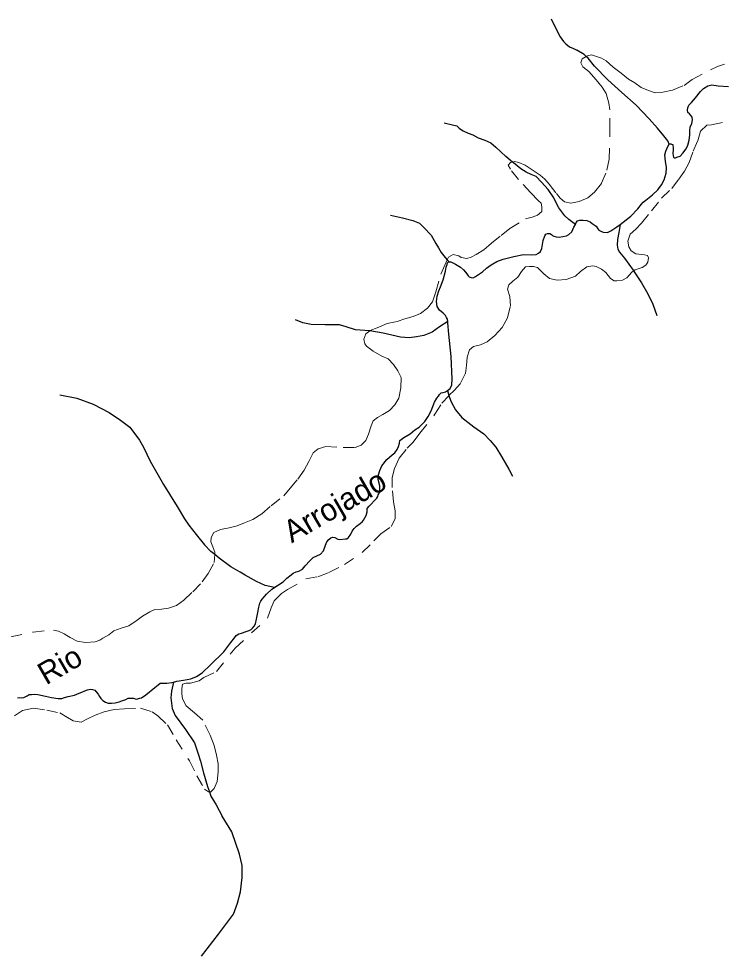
# Model space of a CAD drawing. Extents: x 391.8 to 446, y 8452 to 8507.5.
# Drawn here: x 400.69 to 407.03, y 8463.36 to 8471.81 of the extents above; entities that cross this region are included whole.
import ezdxf
from ezdxf.enums import TextEntityAlignment as Align

# ---------------------------------------------------------------- set-up
doc = ezdxf.new("R2010")
doc.units = 0
doc.header["$LTSCALE"] = 0.064
doc.linetypes.add('LONG_DASHED', pattern=[7.5, 6, -1.5])
doc.linetypes.add('SHORT_DASHED', pattern=[2.7, 1.5, -1.2])
for name, color, linetype, lineweight in [('21', 7, 'SHORT_DASHED', 13), ('7', 7, 'Continuous', 25), ('9', 7, 'LONG_DASHED', 25)]:
    doc.layers.add(name, color=color, linetype=linetype, lineweight=lineweight)
doc.layers.add('61', color=7, linetype='Continuous')

msp = doc.modelspace()

# ---------------------------------------------------------------- linework, layer by layer
at = {"layer": '21'}
for points in [[(405.1393, 8470.5226), (405.1582, 8470.5264), (405.1966, 8470.5187), (405.2541, 8470.4957), (405.3154, 8470.4536), (405.3882, 8470.4038), (405.4304, 8470.3694), (405.4687, 8470.3235), (405.5339, 8470.2392), (405.5684, 8470.1971), (405.6067, 8470.1627), (405.6642, 8470.1512), (405.7409, 8470.1665), (405.8176, 8470.2009), (405.8789, 8470.2507), (405.9402, 8470.3311), (405.9901, 8470.4498), (406.0092, 8470.5493), (406.0169, 8470.8173), (406.0144, 8470.995), (406.0067, 8471.0524), (405.9837, 8471.1405), (405.9454, 8471.1979), (405.8917, 8471.263), (405.8266, 8471.3396), (405.7729, 8471.3817), (405.7537, 8471.4161), (405.7652, 8471.4544), (405.8035, 8471.475)], [(405.8035, 8471.475), (405.8151, 8471.4812), (405.8496, 8471.4889), (405.9416, 8471.4582), (405.9837, 8471.4353), (406.0451, 8471.3778), (406.1179, 8471.3243), (406.1831, 8471.2707), (406.2406, 8471.2362), (406.2981, 8471.1941), (406.3632, 8471.1673), (406.4246, 8471.1482), (406.4936, 8471.152), (406.5817, 8471.1711), (406.6852, 8471.2132), (406.7581, 8471.2668), (406.9229, 8471.3549), (406.9842, 8471.3855), (407.0494, 8471.4046)], [(406.2294, 8469.5409), (406.2454, 8469.5516), (406.3076, 8469.5724), (406.3387, 8469.5931), (406.3594, 8469.6189), (406.3646, 8469.6604), (406.3542, 8469.6811), (406.3283, 8469.6862), (406.2506, 8469.6966), (406.2091, 8469.7225), (406.1884, 8469.7587), (406.178, 8469.8105), (406.1987, 8469.8726), (406.2506, 8469.9192), (406.3024, 8469.971), (406.3923, 8470.0826), (406.4804, 8470.1965), (406.5737, 8470.2845), (406.6359, 8470.3673), (406.6878, 8470.4398), (406.7292, 8470.5175), (406.7655, 8470.621), (406.807, 8470.7142), (406.8329, 8470.8022), (406.8899, 8470.854), (406.9314, 8470.8592), (407.0351, 8470.8799)], [(404.5512, 8469.642), (404.5627, 8469.6662), (404.6048, 8469.6892), (404.6547, 8469.6777), (404.6777, 8469.6624), (404.7275, 8469.6547), (404.7658, 8469.6662), (404.8118, 8469.6892), (404.8808, 8469.7313), (404.9498, 8469.7925), (405.038, 8469.8615), (405.1147, 8469.9227), (405.2565, 8470.0108), (405.3158, 8470.0246), (405.3656, 8470.0437), (405.4039, 8470.0782), (405.4039, 8470.1203), (405.3963, 8470.1509), (405.3694, 8470.1777), (405.3043, 8470.2466), (405.1931, 8470.3653), (405.1203, 8470.4572), (405.1007, 8470.4957), (405.1199, 8470.5187), (405.1393, 8470.5226)], [(403.8528, 8469.0021), (403.8572, 8469.0056), (403.9185, 8469.0286), (404.0105, 8469.0669), (404.0987, 8469.086), (404.1677, 8469.109), (404.2444, 8469.1319), (404.3095, 8469.1587), (404.3748, 8469.2068), (404.417, 8469.2642), (404.4477, 8469.3523), (404.4937, 8469.5131), (404.5282, 8469.5935), (404.5512, 8469.642)], [(404.7516, 8468.8299), (404.7879, 8468.861), (404.8501, 8468.8765), (404.9123, 8468.9024), (404.9797, 8468.9593), (405.0471, 8469.0318), (405.0937, 8469.1198), (405.1196, 8469.2234), (405.1145, 8469.3114), (405.0946, 8469.3756), (405.1049, 8469.417), (405.1412, 8469.4481), (405.1879, 8469.4843), (405.219, 8469.5361), (405.2553, 8469.5775), (405.2916, 8469.5827), (405.3278, 8469.5827), (405.3641, 8469.5724), (405.3952, 8469.5413), (405.4212, 8469.5154), (405.473, 8469.474), (405.5404, 8469.4585), (405.6233, 8469.4636), (405.7063, 8469.4947), (405.7529, 8469.5361), (405.8099, 8469.5775), (405.8618, 8469.5879), (405.8929, 8469.5827), (405.9395, 8469.5568), (405.981, 8469.5258), (406.0225, 8469.474), (406.0536, 8469.4533), (406.0795, 8469.4533), (406.1313, 8469.4585), (406.1676, 8469.4792), (406.2143, 8469.5309), (406.2294, 8469.5409)], [(402.4571, 8466.9837), (402.459, 8467.0068), (402.4399, 8467.0527), (402.4207, 8467.0987), (402.4245, 8467.137), (402.4475, 8467.1829), (402.5089, 8467.2097), (402.5855, 8467.225), (402.6584, 8467.2442), (402.7235, 8467.271), (402.8002, 8467.3016), (402.8807, 8467.3513), (402.965, 8467.4241), (403.078, 8467.5142), (403.1355, 8467.5831), (403.2045, 8467.6635), (403.262, 8467.7438), (403.3042, 8467.8242), (403.3425, 8467.9008), (403.3885, 8467.9391), (403.4575, 8467.9582), (403.6147, 8467.9506), (403.722, 8467.9506), (403.7757, 8467.9697), (403.8178, 8468.0118), (403.8408, 8468.0693), (403.8649, 8468.1442), (403.884, 8468.1902), (403.9224, 8468.2208), (403.9722, 8468.2476), (404.0297, 8468.2821), (404.0795, 8468.3357), (404.114, 8468.3931), (404.1332, 8468.4888), (404.137, 8468.5807), (404.1064, 8468.6419), (404.068, 8468.6993), (404.0182, 8468.7491), (403.9607, 8468.7721), (403.884, 8468.818), (403.8227, 8468.864), (403.8074, 8468.8831), (403.7997, 8468.9252), (403.8189, 8468.975), (403.8528, 8469.0021)], [(404.5666, 8468.4174), (404.6168, 8468.4675), (404.6687, 8468.5245), (404.7153, 8468.6177), (404.7257, 8468.6901), (404.7309, 8468.7626), (404.7516, 8468.8299)], [(402.4086, 8464.8442), (402.421, 8464.8442), (402.4521, 8464.8753), (402.478, 8464.9374), (402.4884, 8465.0254), (402.4884, 8465.0979), (402.4728, 8465.1756), (402.4521, 8465.2636), (402.4158, 8465.3568), (402.3484, 8465.4914), (402.2758, 8465.5587), (402.1981, 8465.6208), (402.167, 8465.6829), (402.1618, 8465.7295), (402.1619, 8465.7733), (402.1671, 8465.8147), (402.1982, 8465.8251), (402.2397, 8465.8251), (402.3175, 8465.8458), (402.3589, 8465.8768), (402.473, 8465.929), (402.6418, 8466.1418), (402.9336, 8466.4116), (402.9641, 8466.5051), (402.9922, 8466.5677), (403.0346, 8466.6088), (403.0568, 8466.6322), (403.113, 8466.6682), (403.2774, 8466.7644), (403.3862, 8466.7851), (403.4847, 8466.8214), (403.6247, 8466.8938), (403.7854, 8467.0026), (403.8904, 8467.1087), (403.9526, 8467.1708), (404.0459, 8467.2381), (404.0822, 8467.3054), (404.0822, 8467.3779), (404.0667, 8467.4607), (404.0563, 8467.5902), (404.0563, 8467.6782), (404.077, 8467.761), (404.1185, 8467.8542), (404.1911, 8467.9422), (404.2429, 8467.9991), (404.3058, 8468.0792), (404.4406, 8468.2501), (404.5028, 8468.3485), (404.565, 8468.4158), (404.5666, 8468.4174)], [(400.6211, 8466.243), (400.8205, 8466.2851), (401.0045, 8466.3043), (401.0505, 8466.2928), (401.1003, 8466.2698), (401.1233, 8466.2545), (401.154, 8466.2354), (401.2191, 8466.2047), (401.292, 8466.1933), (401.3801, 8466.1971), (401.4223, 8466.2124), (401.4491, 8466.2315), (401.5028, 8466.2622), (401.5488, 8466.2966), (401.614, 8466.3196), (401.683, 8466.3426), (401.7596, 8466.3923), (401.8056, 8466.4306), (401.8708, 8466.4689), (401.9184, 8466.4885), (401.9759, 8466.4924), (402.0411, 8466.5), (402.1139, 8466.5268), (402.1791, 8466.5728), (402.2596, 8466.6493), (402.3439, 8466.7374), (402.3976, 8466.8139), (402.4512, 8466.9135), (402.4571, 8466.9837)], [(400.6529, 8465.5313), (400.7255, 8465.5779), (400.824, 8465.5986), (400.9432, 8465.583), (401.0624, 8465.5571), (401.1298, 8465.5157), (401.1816, 8465.4847), (401.2542, 8465.4743), (401.3061, 8465.5002), (401.3786, 8465.5364), (401.4616, 8465.5675), (401.5497, 8465.5882), (401.643, 8465.5934), (401.7882, 8465.5986), (401.8918, 8465.5675), (401.9437, 8465.5313), (402.0318, 8465.4484), (402.1099, 8465.3154), (402.2292, 8465.1238), (402.2966, 8464.9892), (402.3639, 8464.8701), (402.4002, 8464.8442), (402.4086, 8464.8442)]]:
    msp.add_lwpolyline(points, dxfattribs=at)
at = {"layer": '7'}
for points in [[(405.8035, 8471.475), (405.7831, 8471.4933), (405.718, 8471.5316)], [(406.5506, 8470.6848), (406.5376, 8470.7131), (406.5031, 8470.759), (406.4456, 8470.8278), (406.369, 8470.912), (406.2542, 8471.0344), (406.1239, 8471.1491), (405.9976, 8471.2638), (405.8789, 8471.3862), (405.8214, 8471.4589), (405.8035, 8471.475)], [(406.5506, 8470.6848), (406.5558, 8470.6874), (406.5662, 8470.6874), (406.5714, 8470.6848), (406.5818, 8470.6796), (406.5844, 8470.6719), (406.587, 8470.6537), (406.587, 8470.6303), (406.5844, 8470.6044), (406.587, 8470.5784), (406.5896, 8470.5655), (406.5974, 8470.5603), (406.6078, 8470.5603), (406.6208, 8470.5655), (406.6493, 8470.5758), (406.6727, 8470.6044), (406.7039, 8470.6433), (406.7169, 8470.6744), (406.7299, 8470.7212), (406.7351, 8470.7653), (406.7377, 8470.8068), (406.7403, 8470.8379), (406.7533, 8470.8717), (406.7611, 8470.9028), (406.7585, 8470.9262), (406.7481, 8470.9392), (406.7325, 8470.9573), (406.7195, 8470.9703), (406.7143, 8470.9911), (406.7195, 8471.0118), (406.7273, 8471.0352), (406.7507, 8471.0611), (406.7871, 8471.1027), (406.832, 8471.158), (406.8606, 8471.1865), (406.8995, 8471.2099), (406.9333, 8471.2176), (406.9905, 8471.2099), (407.084, 8471.2047)], [(405.1393, 8470.5226), (405.0792, 8470.5726), (404.9884, 8470.6557)], [(406.1076, 8469.9592), (406.2063, 8470.0336), (406.2687, 8470.1011), (406.2999, 8470.1426), (406.3155, 8470.1608), (406.3389, 8470.179), (406.3999, 8470.2266), (406.4467, 8470.2733), (406.4805, 8470.3174), (406.5064, 8470.3615), (406.5246, 8470.4212), (406.5272, 8470.4731), (406.5168, 8470.5302), (406.5116, 8470.5873), (406.5194, 8470.621), (406.5376, 8470.6641), (406.5506, 8470.6848)], [(405.7074, 8469.961), (405.6475, 8470.0052), (405.6097, 8470.0392), (405.556, 8470.1116), (405.5068, 8470.2098), (405.4614, 8470.2741), (405.4008, 8470.3421), (405.3516, 8470.3912), (405.3062, 8470.4101), (405.2608, 8470.4328), (405.2154, 8470.463), (405.1473, 8470.5159), (405.1393, 8470.5226)], [(404.5678, 8469.6233), (404.5834, 8469.6233), (404.625, 8469.6026), (404.6692, 8469.5766), (404.6978, 8469.5507), (404.716, 8469.5299), (404.7263, 8469.5143), (404.7393, 8469.4962), (404.7497, 8469.4884), (404.7653, 8469.4806), (404.7861, 8469.478), (404.8043, 8469.491), (404.8693, 8469.5325), (404.9056, 8469.5662), (404.9472, 8469.5974), (404.9966, 8469.6259), (405.0538, 8469.6467), (405.1525, 8469.6726), (405.2383, 8469.6882), (405.3119, 8469.6855), (405.3535, 8469.6907), (405.3743, 8469.701), (405.3925, 8469.7166), (405.4029, 8469.7426), (405.4159, 8469.8152), (405.4289, 8469.8567), (405.4393, 8469.8723), (405.4549, 8469.8775), (405.4756, 8469.8775), (405.4912, 8469.8697), (405.499, 8469.8619), (405.512, 8469.8541), (405.5328, 8469.849), (405.5588, 8469.8464), (405.5926, 8469.8516), (405.6264, 8469.8567), (405.6471, 8469.8697), (405.6731, 8469.8931), (405.6913, 8469.9346), (405.7074, 8469.961)], [(405.7074, 8469.961), (405.7126, 8469.9791), (405.7256, 8469.9921), (405.7464, 8469.9999), (405.775, 8469.9999), (405.8088, 8469.9947), (405.8374, 8469.9843), (405.8555, 8469.9688), (405.8919, 8469.9454), (405.9075, 8469.922), (405.9179, 8469.9091), (405.9361, 8469.8987), (405.9569, 8469.8909), (405.9959, 8469.8883), (406.0244, 8469.9039), (406.079, 8469.9376), (406.1076, 8469.9592)], [(406.1076, 8469.9592), (406.0972, 8469.8882), (406.0861, 8469.8246), (406.0833, 8469.7748), (406.0889, 8469.7389), (406.1027, 8469.7112), (406.147, 8469.6559), (406.2245, 8469.5481), (406.2294, 8469.5409)], [(404.5557, 8469.0857), (404.5523, 8469.1076), (404.5445, 8469.1206), (404.5367, 8469.1388), (404.5159, 8469.1595), (404.4821, 8469.1881), (404.4613, 8469.2218), (404.4535, 8469.2659), (404.4613, 8469.3126), (404.4743, 8469.362), (404.4899, 8469.3983), (404.5159, 8469.4606), (404.5341, 8469.5403), (404.5418, 8469.574), (404.5496, 8469.6), (404.5548, 8469.6129), (404.56, 8469.6207), (404.5678, 8469.6233)], [(406.2294, 8469.5409), (406.302, 8469.4347), (406.3574, 8469.3352), (406.4017, 8469.2412), (406.4377, 8469.1389)], [(404.555, 8468.4625), (404.5782, 8468.4805), (404.5938, 8468.5143), (404.5964, 8468.5662), (404.586, 8468.7686), (404.5652, 8468.971), (404.5575, 8469.0739), (404.5557, 8469.0857)], [(402.9939, 8466.6872), (402.9985, 8466.6901), (403.0323, 8466.7109), (403.0739, 8466.7394), (403.1076, 8466.7706), (403.144, 8466.8017), (403.1648, 8466.8173), (403.1908, 8466.8277), (403.2142, 8466.8355), (403.248, 8466.8536), (403.2713, 8466.8822), (403.3129, 8466.9289), (403.3441, 8466.9574), (403.3779, 8466.973), (403.4091, 8466.9886), (403.4351, 8467.0171), (403.4532, 8467.069), (403.4669, 8467.0984), (403.4851, 8467.1191), (403.5033, 8467.1347), (403.5189, 8467.1399), (403.5397, 8467.1373), (403.5656, 8467.1243), (403.5838, 8467.1191), (403.6335, 8467.1251), (403.6465, 8467.1277), (403.662, 8467.1381), (403.6828, 8467.1692), (403.6958, 8467.1952), (403.714, 8467.2185), (403.7348, 8467.2393), (403.766, 8467.2652), (403.7868, 8467.2834), (403.7972, 8467.2938), (403.8102, 8467.3145), (403.8206, 8467.3353), (403.8284, 8467.369), (403.831, 8467.4002), (403.8465, 8467.4209), (403.8673, 8467.4391), (403.8933, 8467.4702), (403.9167, 8467.4936), (403.9245, 8467.5066), (403.9297, 8467.5222), (403.9427, 8467.5481), (403.9453, 8467.5792), (403.9427, 8467.6052), (403.9297, 8467.6623), (403.9323, 8467.7038), (403.9427, 8467.7427), (403.9615, 8467.7857), (404.0057, 8467.8402), (404.055, 8467.8843), (404.0784, 8467.9025), (404.0992, 8467.931), (404.1122, 8467.9596), (404.12, 8467.9881), (404.1252, 8468.0115), (404.1356, 8468.0219), (404.1616, 8468.04), (404.2162, 8468.0738), (404.2603, 8468.1075), (404.2993, 8468.1334), (404.3487, 8468.1828), (404.3799, 8468.2295), (404.4058, 8468.2788), (404.4379, 8468.3585), (404.4587, 8468.3949), (404.4717, 8468.413), (404.4821, 8468.4286), (404.4951, 8468.4416), (404.5133, 8468.4468), (404.5367, 8468.452), (404.5548, 8468.4623), (404.555, 8468.4625)], [(402.4571, 8466.9837), (402.4219, 8467.0118), (402.3638, 8467.0734)], [(402.6848, 8466.8258), (402.6024, 8466.8736), (402.4971, 8466.9517), (402.4571, 8466.9837)], [(402.9939, 8466.6872), (402.9123, 8466.7053), (402.8341, 8466.7414), (402.7318, 8466.7985), (402.6848, 8466.8258)], [(402.0852, 8465.8352), (402.1166, 8465.8422), (402.1763, 8465.8526), (402.2413, 8465.8656), (402.2933, 8465.8863), (402.3426, 8465.9175), (402.4182, 8465.9903), (402.5378, 8466.1071), (402.6027, 8466.1927), (402.6353, 8466.2345), (402.6513, 8466.255), (402.6747, 8466.2696), (402.6981, 8466.2769), (402.7405, 8466.2915), (402.7668, 8466.3002), (402.7843, 8466.3104), (402.7975, 8466.3206), (402.8121, 8466.3382), (402.8238, 8466.36), (402.834, 8466.4024), (402.8442, 8466.4622), (402.853, 8466.5104), (402.8632, 8466.5468), (402.8734, 8466.5658), (402.8837, 8466.5833), (402.9056, 8466.6052), (402.9246, 8466.6286), (402.9699, 8466.672), (402.9939, 8466.6872)], [(400.6801, 8465.6937), (400.6957, 8465.6963), (400.7139, 8465.6937), (400.7373, 8465.6963), (400.7554, 8465.7041), (400.7658, 8465.7118), (400.784, 8465.7222), (400.8048, 8465.7222), (400.8308, 8465.7248), (400.862, 8465.7222), (400.9326, 8465.709), (400.9872, 8465.696), (401.047, 8465.6883), (401.0807, 8465.6883), (401.1041, 8465.696), (401.1379, 8465.7038), (401.1925, 8465.7168), (401.2366, 8465.735), (401.26, 8465.7454), (401.286, 8465.7557), (401.312, 8465.7661), (401.3354, 8465.7713), (401.3562, 8465.7687), (401.377, 8465.7609), (401.3874, 8465.7479), (401.4056, 8465.7246), (401.4185, 8465.7038), (401.4315, 8465.6857), (401.4497, 8465.6675), (401.4731, 8465.6545), (401.4965, 8465.6441), (401.5277, 8465.6441), (401.5589, 8465.6493), (401.5953, 8465.6571), (401.6186, 8465.6649), (401.655, 8465.6779), (401.6769, 8465.6886), (401.6951, 8465.6912), (401.7237, 8465.6886), (401.7497, 8465.6808), (401.7809, 8465.6886), (401.7965, 8465.6938), (401.8355, 8465.7197), (401.916, 8465.7872), (401.9477, 8465.8111), (401.9658, 8465.8241), (401.9892, 8465.8267), (402.0256, 8465.8267), (402.0698, 8465.8318), (402.0852, 8465.8352)], [(402.0852, 8465.8352), (402.068, 8465.7536), (402.062, 8465.6915), (402.0743, 8465.597), (402.1017, 8465.533), (402.1933, 8465.4079), (402.2758, 8465.286), (402.3063, 8465.1884), (402.3277, 8465.1213), (402.3551, 8465.0177), (402.3918, 8464.8927), (402.4086, 8464.8442)], [(402.4086, 8464.8442), (402.4211, 8464.8079), (402.4698, 8464.7299), (402.524, 8464.6249)]]:
    msp.add_lwpolyline(points, dxfattribs=at)
at = {"layer": '9'}
msp.add_line((404.555, 8468.4625), (404.5666, 8468.4174), dxfattribs=at)
for points in [[(405.4882, 8471.8146), (405.538, 8471.7075), (405.5686, 8471.6501), (405.5993, 8471.6081), (405.6184, 8471.5889), (405.6529, 8471.5622), (405.6874, 8471.5469), (405.718, 8471.5316)], [(404.5231, 8470.8749), (404.5987, 8470.8597), (404.6366, 8470.8484), (404.6593, 8470.8295), (404.6706, 8470.8182), (404.6933, 8470.8031), (404.7387, 8470.7842), (404.7803, 8470.7691), (404.8295, 8470.7426), (404.8901, 8470.7199), (404.943, 8470.6973), (404.9884, 8470.6557)], [(404.0386, 8470.0438), (404.1483, 8470.0214), (404.2412, 8469.9961), (404.3003, 8469.9708), (404.3397, 8469.9342), (404.4073, 8469.864), (404.4495, 8469.7881), (404.472, 8469.7487), (404.4973, 8469.7065), (404.5339, 8469.6616), (404.5512, 8469.642), (404.5678, 8469.6233)], [(403.8528, 8469.0021), (403.8499, 8469.0026), (403.7248, 8469.0118), (403.6393, 8469.0362), (403.5813, 8469.0544), (403.4501, 8469.0544), (403.325, 8469.0575), (403.2517, 8469.0727), (403.1846, 8469.1002)], [(404.5557, 8469.0857), (404.4816, 8469.0362), (404.4144, 8468.9904), (404.3412, 8468.96), (404.2741, 8468.9478), (404.2069, 8468.9386), (404.1306, 8468.9447), (403.975, 8468.9813), (403.8528, 8469.0021)], [(401.0603, 8468.4241), (401.2138, 8468.394), (401.3612, 8468.34), (401.5056, 8468.2649), (401.6079, 8468.1957), (401.692, 8468.1342), (401.7806, 8468.0143), (401.8152, 8467.9527), (401.8756, 8467.8262), (401.996, 8467.6159), (402.1171, 8467.419), (402.1833, 8467.3078), (402.2224, 8467.2507), (402.2886, 8467.1666), (402.3638, 8467.0734)], [(404.5666, 8468.4174), (404.5709, 8468.4005), (404.5853, 8468.3609), (404.6249, 8468.289), (404.6825, 8468.2207), (404.7904, 8468.1345), (404.8804, 8468.0734), (404.938, 8468.0123), (404.9884, 8467.9512), (405.0388, 8467.8685), (405.1071, 8467.7535), (405.1395, 8467.6924)], [(402.3386, 8463.3635), (402.4898, 8463.5631), (402.6264, 8463.7434), (402.6605, 8463.8408), (402.6898, 8463.9431), (402.7044, 8464.0746), (402.7044, 8464.1817), (402.68, 8464.284), (402.6117, 8464.4837), (402.524, 8464.6249)]]:
    msp.add_lwpolyline(points, dxfattribs=at)

# ---------------------------------------------------------------- texts
at = {"layer": '61'}
msp.add_text('Rio                             Arrojado', height=0.2, rotation=30.055, dxfattribs=at).set_placement((402.4812, 8466.6975), align=Align.CENTER)

doc.saveas('drawing.dxf')
